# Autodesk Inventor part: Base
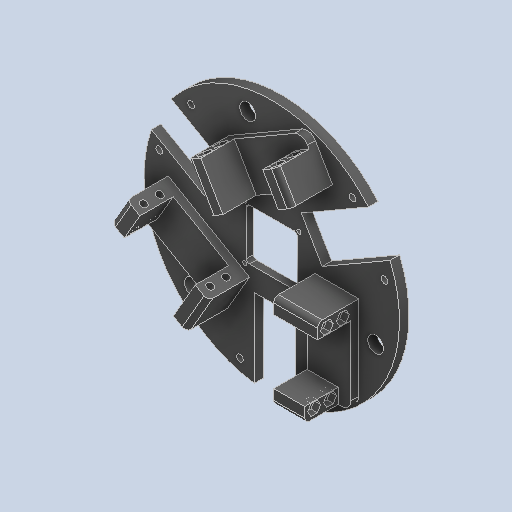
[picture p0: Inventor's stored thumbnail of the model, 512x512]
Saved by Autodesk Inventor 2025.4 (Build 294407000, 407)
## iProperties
Created: 2026-09
Part Number: Base
Material: Generic
Document SubType Name: Modeling
Designer: AdminForWorker
Density: 1 g/cm^3
Appearance: Default
Title: Base v9 v2
Author: AdminForWorker
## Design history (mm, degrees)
feature "Body1"
body "Solid1"
